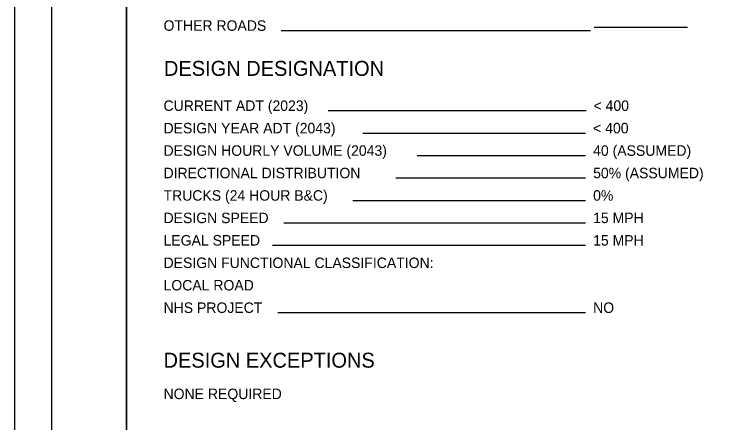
# Model space of a CAD drawing. Extents: x -13.1 to 43.1, y 0 to 22.
# Drawn here: x 0 to 9.59, y 5.64 to 11.1 of the extents above; entities that cross this region are included whole.
import ezdxf

# ---------------------------------------------------------------- set-up
doc = ezdxf.new("R2010")
doc.units = 0
for name, color, linetype in [('SH_Border', 7, 'Continuous'), ('SH_Data', 7, 'Continuous'), ('SH_Text', 7, 'Continuous')]:
    doc.layers.add(name, color=color, linetype=linetype)

msp = doc.modelspace()

# ---------------------------------------------------------------- linework, layer by layer
at = {"layer": 'SH_Border'}
for points in [[(0.5, 21.5), (1.5, 21.5), (1.5, 0.5), (0.5, 0.5)], [(1.5, 21.5), (33.5, 21.5), (33.5, 0.5), (1.5, 0.5)]]:
    msp.add_lwpolyline(points, close=True, dxfattribs=at)
at = {"layer": 'SH_Data'}
for p, q in [((7.7, 10.8767), (3.5657, 10.8767)), ((9, 10.9223), (7.75, 10.9223)), ((7.6424, 9.8062), (4.1936, 9.8062)), ((7.6368, 9.5062), (4.6592, 9.5062)), ((7.6368, 9.2062), (5.3852, 9.2062)), ((7.6368, 8.9062), (5.0988, 8.9062)), ((7.6368, 8.6062), (4.5259, 8.6062)), ((7.6368, 8.3062), (3.6035, 8.3062)), ((7.6368, 8.0062), (3.4488, 8.0062)), ((7.6368, 7.1062), (3.5243, 7.1062))]:
    msp.add_line(p, q, dxfattribs=at)
msp.add_lwpolyline([(0, 0), (34, 0), (34, 22), (0, 22)], close=True, dxfattribs=at)

# ---------------------------------------------------------------- texts
msp.add_text('DESIGN DESIGNATION', height=0.2, dxfattribs=at).set_placement((2, 10.2747))
at = {"layer": 'SH_Text'}
for s, height, p in [('OTHER ROADS', 0.14, (1.9944, 10.8767)), ('CURRENT ADT (2023)', 0.14, (1.9944, 9.8062)), ('< 400', 0.14, (7.7424, 9.8062)), ('DESIGN YEAR ADT (2043)', 0.14, (1.9944, 9.5062)), ('< 400', 0.14, (7.7368, 9.5062)), ('DESIGN HOURLY VOLUME (2043)', 0.14, (1.9944, 9.2062)), ('40 (ASSUMED)', 0.14, (7.7368, 9.2062)), ('DIRECTIONAL DISTRIBUTION', 0.14, (1.9944, 8.9062)), ('50% (ASSUMED)', 0.14, (7.7368, 8.9062)), ('TRUCKS (24 HOUR B&C)', 0.14, (1.9944, 8.6062)), ('0%', 0.14, (7.7368, 8.6062)), ('DESIGN SPEED', 0.14, (1.9944, 8.3062)), ('15 MPH', 0.14, (7.7368, 8.3062)), ('LEGAL SPEED', 0.14, (1.9944, 8.0062)), ('15 MPH', 0.14, (7.7368, 8.0062)), ('DESIGN FUNCTIONAL CLASSIFICATION:', 0.14, (1.9944, 7.7062)), ('LOCAL ROAD', 0.14, (1.9944, 7.4062)), ('NHS PROJECT', 0.14, (1.9944, 7.1062)), ('NO', 0.14, (7.7368, 7.1062)), ('DESIGN EXCEPTIONS', 0.2, (1.9944, 6.3744)), ('NONE REQUIRED', 0.14, (1.9944, 5.9544))]:
    msp.add_text(s, height=height, dxfattribs=at).set_placement(p)

doc.saveas('drawing.dxf')
